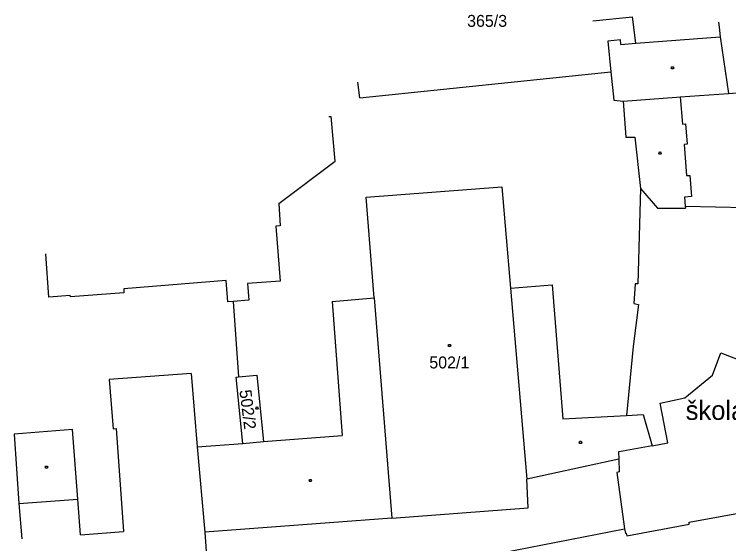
# Model space of a CAD drawing. Extents: x -859779 to -859412, y -1098786 to -1098252.
# Drawn here: x -859730.4 to -859628.8, y -1098327.1 to -1098251.7 of the extents above; entities that cross this region are included whole.
import ezdxf

# ---------------------------------------------------------------- set-up
doc = ezdxf.new("R2010")
doc.units = 0
for name, color, linetype in [('Vrstva 16', 7, 'Continuous'), ('Vrstva 19', 7, 'Continuous'), ('Vrstva 4', 7, 'Continuous')]:
    doc.layers.add(name, color=color, linetype=linetype)

msp = doc.modelspace()

# ---------------------------------------------------------------- linework, layer by layer
at = {"layer": 'Vrstva 4'}
for p, q in [((-859648.11, -1098252.64), (-859642.45, -1098252.03)), ((-859641.99, -1098255.82), (-859642.45, -1098252.03)), ((-859630.23, -1098252.82), (-859630.15, -1098253.54)), ((-859630.15, -1098253.54), (-859629.99, -1098254.91)), ((-859641.99, -1098255.82), (-859629.99, -1098254.91)), ((-859629.99, -1098254.91), (-859628.79, -1098262.96)), ((-859644.17, -1098255.35), (-859645.96, -1098255.5)), ((-859645.96, -1098255.5), (-859645.53, -1098259.89)), ((-859644.13, -1098256.01), (-859644.17, -1098255.35)), ((-859644.13, -1098256.01), (-859641.99, -1098255.82)), ((-859681.29, -1098263.59), (-859645.53, -1098259.89)), ((-859645.53, -1098259.89), (-859645.13, -1098263.91)), ((-859681.29, -1098263.59), (-859681.54, -1098261.36)), ((-859628.79, -1098262.96), (-859614.78, -1098261.97)), ((-859636.23, -1098263.48), (-859635.68, -1098263.44)), ((-859635.68, -1098263.44), (-859628.79, -1098262.96)), ((-859635.68, -1098263.44), (-859635.37, -1098267.32)), ((-859645.13, -1098263.91), (-859643.79, -1098264.05)), ((-859643.79, -1098264.05), (-859636.23, -1098263.48)), ((-859643.79, -1098264.05), (-859643.44, -1098269.19)), ((-859685.68, -1098266.25), (-859685.34, -1098266.23)), ((-859684.79, -1098272.6), (-859685.34, -1098266.23)), ((-859635.37, -1098267.32), (-859634.92, -1098267.28)), ((-859634.92, -1098267.28), (-859634.68, -1098270.19)), ((-859643.44, -1098269.19), (-859642.13, -1098269.17)), ((-859642.13, -1098269.17), (-859641.34, -1098276.5)), ((-859634.68, -1098270.19), (-859635.14, -1098270.23)), ((-859635.14, -1098270.23), (-859634.78, -1098274.66)), ((-859692.8, -1098278.65), (-859684.79, -1098272.6)), ((-859634.78, -1098274.66), (-859634.33, -1098274.63)), ((-859634.33, -1098274.63), (-859634.08, -1098277.65)), ((-859680.35, -1098277.72), (-859661.06, -1098276.28)), ((-859661.06, -1098276.28), (-859659.85, -1098290.68)), ((-859641.34, -1098276.5), (-859641.69, -1098290.06)), ((-859641.34, -1098276.5), (-859638.93, -1098279.29)), ((-859634.08, -1098277.65), (-859635.08, -1098277.73)), ((-859692.8, -1098278.65), (-859692.59, -1098281.8)), ((-859679.23, -1098292.09), (-859680.35, -1098277.72)), ((-859635.08, -1098277.73), (-859634.98, -1098279.03)), ((-859638.93, -1098279.29), (-859634.95, -1098279.32)), ((-859634.98, -1098279.03), (-859634.95, -1098279.32)), ((-859634.98, -1098279.03), (-859619.82, -1098279.35)), ((-859692.59, -1098281.8), (-859693.21, -1098281.88)), ((-859693.21, -1098281.88), (-859692.62, -1098289.68)), ((-859725.51, -1098291.96), (-859725.96, -1098285.81)), ((-859700.29, -1098289.62), (-859714.87, -1098290.79)), ((-859700.25, -1098290.22), (-859700.29, -1098289.62)), ((-859692.62, -1098289.68), (-859697.26, -1098290.01)), ((-859714.87, -1098290.79), (-859714.83, -1098291.38)), ((-859700.05, -1098292.64), (-859700.25, -1098290.22)), ((-859697.26, -1098290.01), (-859697.08, -1098292.4)), ((-859659.85, -1098290.68), (-859653.9, -1098290.21)), ((-859659.85, -1098290.68), (-859657.53, -1098317.91)), ((-859653.9, -1098290.21), (-859652.4, -1098309.32)), ((-859642.1, -1098290.06), (-859642.27, -1098292.88)), ((-859641.69, -1098290.06), (-859642.1, -1098290.06)), ((-859722.48, -1098291.73), (-859725.51, -1098291.96)), ((-859722.46, -1098291.93), (-859722.48, -1098291.73)), ((-859714.83, -1098291.38), (-859722.46, -1098291.93)), ((-859699.31, -1098292.58), (-859700.05, -1098292.64)), ((-859697.08, -1098292.4), (-859699.31, -1098292.58)), ((-859699.31, -1098292.58), (-859698.53, -1098303.32)), ((-859685.22, -1098292.58), (-859679.23, -1098292.09)), ((-859685.22, -1098292.58), (-859683.77, -1098311.67)), ((-859679.23, -1098292.09), (-859676.73, -1098323.43)), ((-859642.27, -1098292.88), (-859641.6, -1098293.02)), ((-859641.6, -1098293.02), (-859642.36, -1098298.98)), ((-859642.36, -1098298.98), (-859643.34, -1098308.82)), ((-859631.1, -1098303.07), (-859629.91, -1098299.9)), ((-859629.91, -1098299.9), (-859624.37, -1098302.06)), ((-859705.26, -1098302.83), (-859716.93, -1098303.71)), ((-859705.26, -1098302.83), (-859704.4, -1098313.28)), ((-859698.53, -1098303.32), (-859695.94, -1098303.09)), ((-859695.94, -1098303.09), (-859694.99, -1098312.55)), ((-859635.01, -1098306.32), (-859631.1, -1098303.07)), ((-859716.93, -1098303.71), (-859716.39, -1098310.71)), ((-859698.88, -1098303.35), (-859698.53, -1098303.32)), ((-859697.94, -1098312.79), (-859698.88, -1098303.35)), ((-859638.55, -1098307.05), (-859635.01, -1098306.32)), ((-859637.43, -1098312.74), (-859638.55, -1098307.05)), ((-859652.4, -1098309.32), (-859643.34, -1098308.82)), ((-859643.34, -1098308.82), (-859640.94, -1098308.69)), ((-859640.94, -1098308.69), (-859639.67, -1098313.13)), ((-859722.17, -1098310.83), (-859730.44, -1098311.46)), ((-859721.39, -1098320.72), (-859722.17, -1098310.83)), ((-859716.39, -1098310.71), (-859715.96, -1098310.68)), ((-859715.96, -1098310.68), (-859714.91, -1098325.36)), ((-859730.44, -1098311.46), (-859729.78, -1098321.37)), ((-859694.99, -1098312.55), (-859683.77, -1098311.67)), ((-859704.4, -1098313.28), (-859697.94, -1098312.79)), ((-859704.4, -1098313.28), (-859703.32, -1098325.46)), ((-859697.94, -1098312.79), (-859694.99, -1098312.55)), ((-859639.67, -1098313.13), (-859643.85, -1098313.89)), ((-859639.67, -1098313.13), (-859637.43, -1098312.74)), ((-859643.85, -1098313.89), (-859644.46, -1098314.02)), ((-859644.46, -1098314.02), (-859644.43, -1098315.05)), ((-859644.43, -1098315.05), (-859657.53, -1098317.91)), ((-859644.43, -1098315.05), (-859644.38, -1098316.85)), ((-859644.38, -1098316.85), (-859644.71, -1098316.92)), ((-859644.71, -1098316.92), (-859643.61, -1098324.96)), ((-859657.31, -1098321.95), (-859657.53, -1098317.91)), ((-859729.78, -1098321.37), (-859721.39, -1098320.72)), ((-859729.78, -1098321.37), (-859729.39, -1098326.41)), ((-859721, -1098325.81), (-859721.39, -1098320.72)), ((-859676.73, -1098323.43), (-859657.31, -1098321.95)), ((-859634.42, -1098324.02), (-859624.17, -1098322.15)), ((-859676.73, -1098323.43), (-859703.32, -1098325.46)), ((-859643.29, -1098325.98), (-859634.39, -1098324.31)), ((-859634.39, -1098324.31), (-859634.42, -1098324.02)), ((-859721, -1098325.81), (-859714.91, -1098325.36)), ((-859703.32, -1098325.46), (-859702.59, -1098336.13)), ((-859661.11, -1098328.36), (-859643.61, -1098324.96)), ((-859643.61, -1098324.96), (-859643.49, -1098325.6)), ((-859643.49, -1098325.6), (-859643.37, -1098325.58)), ((-859643.37, -1098325.58), (-859643.29, -1098325.98))]:
    msp.add_line(p, q, dxfattribs=at)
for points in [[(-859636.7, -1098259.18), (-859636.61, -1098259.33), (-859636.7, -1098259.48), (-859636.88, -1098259.48), (-859636.97, -1098259.33), (-859636.88, -1098259.18)], [(-859638.47, -1098271.3), (-859638.38, -1098271.45), (-859638.47, -1098271.6), (-859638.65, -1098271.6), (-859638.74, -1098271.45), (-859638.65, -1098271.3)], [(-859668.43, -1098298.71), (-859668.34, -1098298.86), (-859668.43, -1098299.01), (-859668.61, -1098299.01), (-859668.7, -1098298.86), (-859668.61, -1098298.71)], [(-859695.81, -1098307.61), (-859695.72, -1098307.76), (-859695.81, -1098307.91), (-859695.99, -1098307.91), (-859696.08, -1098307.76), (-859695.99, -1098307.61)], [(-859649.79, -1098312.5), (-859649.7, -1098312.65), (-859649.79, -1098312.8), (-859649.97, -1098312.8), (-859650.06, -1098312.65), (-859649.97, -1098312.5)], [(-859725.76, -1098316.04), (-859725.67, -1098316.19), (-859725.76, -1098316.34), (-859725.94, -1098316.34), (-859726.03, -1098316.19), (-859725.94, -1098316.04)], [(-859688.22, -1098317.92), (-859688.13, -1098318.07), (-859688.22, -1098318.22), (-859688.4, -1098318.22), (-859688.49, -1098318.07), (-859688.4, -1098317.92)]]:
    msp.add_lwpolyline(points, close=True, dxfattribs=at)

# ---------------------------------------------------------------- texts
at = {"layer": 'Vrstva 16'}
msp.add_text('škola', height=2.72, dxfattribs=at).set_placement((-859634.908, -1098309.45))
at = {"layer": 'Vrstva 19'}
for s, p in [('365/3', (-859666.003, -1098253.48)), ('502/1', (-859671.383, -1098302.12))]:
    msp.add_text(s, height=1.7, dxfattribs=at).set_placement(p)
msp.add_text('502/2', height=1.7, rotation=277.19698, dxfattribs=at).set_placement((-859698.41, -1098305.256))

doc.saveas('drawing.dxf')
